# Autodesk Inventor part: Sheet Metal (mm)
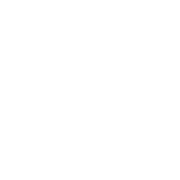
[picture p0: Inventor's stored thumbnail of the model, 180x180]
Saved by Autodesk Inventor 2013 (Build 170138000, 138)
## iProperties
Shininess: 64.0
Length Units: 11269
Angle Units: 11279
Time Units: 11290
Mass Units: 11283
Length Display Precision: 3
Angle Display Precision: 2
Compacted: True
Part Number: Sheet Metal (mm)
Document SubType Name: Sheet Metal
Created: 2002-07
Density: 1 g/cm^3
Sheet Metal Rule: Default
Material: Generic
Density: 0.0
Volumn: 0.0
Area: 0.0
PropertySet Name: Model Information
Control State: 0
Master: False
Checked Out: False
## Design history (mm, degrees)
other parameters: "Thickness" = 0.5, "BendRadius" = 0.5 (= Thickness), "BendReliefWidth" = 0.5 (= Thickness), "BendReliefDepth" = 0.25 (= 0.5 x Thickness), "CornerReliefSize" = 2 (= 4 x Thickness), "SeamGap" = 0.01, "MinimumRemnant" = 1 (= 2 x Thickness), "TransitionRadius" = 0.5 (= BendRadius), "JacobiRadiusSize" = 0.5 (= BendRadius), "GapSize" = 0.5 (= Thickness)
